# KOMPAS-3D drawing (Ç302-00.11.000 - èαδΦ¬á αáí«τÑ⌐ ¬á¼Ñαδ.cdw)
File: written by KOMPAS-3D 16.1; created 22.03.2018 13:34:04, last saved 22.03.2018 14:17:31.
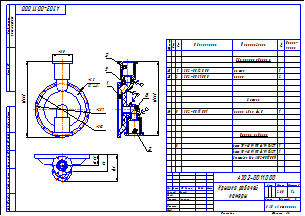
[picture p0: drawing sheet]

Sheet 1: A3, landscape

Title block, sheet 1: name: Крышка рабочей / камеры; designation: А302-00.11.000; mass: 2,68; scale: 1:4; sheets: 1; organisation: ЗАО «Астерион»; sheet format: A3; stored path: Z:\Мембранные насосы\Мембранный электропривод\А302-00.00.000 - ASTRA-302 (МЭ200)\Чертежи\А302-00.11.000 - Крышка рабочей камеры.cdw; drawn by: Милов; technical control: Лучихин

Views: Вид 1, Местный разрез 1, Вид:1, Проекционный вид 2, Проекционный вид 3
Referenced files in Z:\1 ПКИ 3D\Полипропиленовые фитинги, трубы\: Колено 90гр 40 FV PPR ф. FV PLAST.m3d, Труба ф40х3,7 (PN10) FV PPR ф. FV PLAST.m3d, Колено 45гр 40 FV PPR ф. FV PLAST.m3d
Referenced files in Z:\Мембранные насосы\Мембранный электропривод\А302-00.00.000 - ASTRA-302 (МЭ200)\3Д\: А302-00.12.001 - Крышка.m3d, А302-00.31.001 - Корпус.m3d, А302-00.11.000 - Крышка рабочей камеры.a3d, А302-00.12.000 - Крышка.a3d, А302-00.11.001 - Колена 45гр ф40.m3d, А302-00.31.000 - Корпус.a3d
Referenced files in Z:\Мембранные насосы\Мембранный электропривод\А302-00.00.000 - ASTRA-302 (МЭ200)\Чертежи\: А302-00.12.000 - Крышка.cdw, А302-00.11.001 - Колено 45гр ф40.cdw, А302-00.31.000 - Корпус.cdw
Referenced files: GRAPHIC.TDP
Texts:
  Крышка
  Колено 45гр ф40
  Корпус
  Колено 90   40 FV PPR ф. "FV PLAST"
  Колено 90@1~ @2~40 FV PPR ф. "FV PLAST"
  (Заготовка для А302-00.11.001)
  Колено 90@1~ @2~40 FV PPR ф. "FV PLAST" / (Заготовка для А302-00.11.001)
  Лит-Масса-Масштаб
  Материал-Предприятие
  Title Specification
  Body Specification ( left align )
  Body Specificaton ( centered )
  Поз.
  Кол.
  Приме-
  чание
  Таблица спецификации
  Труба ф40х3,7 (PN10) FV PPR ф. FV PLAST
  Колено 45гр 40 FV PPR ф. FV PLAST
  Колено 90гр 40 FV PPR ф. FV PLAST
Dimensions and other numbers on the sheet: 410,31; 2; 1; 5; 8; 419,81; 302; 287; 6,5; 12 отв.; 110; 58,82; 93; 148; 4; 9; 1:4; 2,68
